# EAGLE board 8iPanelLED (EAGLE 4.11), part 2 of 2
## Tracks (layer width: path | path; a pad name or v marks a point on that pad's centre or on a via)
+15V
  Top 0.762: R75.1 375.29,80.01 375.29,90.17 R74.1 375.29,90.81 375.29,101.6 R73.1 | R81.1 326.39,46.35 326.39,56.52 R80.1 326.39,57.78 326.39,67.94 R79.1 326.39,68.58 326.39,78.74 R78.1 326.39,80.01 326.39,90.17 R77.1 326.39,90.81 326.39,100.97 R76.1 | 232.41,12.7 232.41,13.97 R64.1 | 232.41,12.7 232.41,12.06 220.34,12.06 218.44,13.97 R63.1 217.81,13.97 209.55,13.97 209.55,13.34 208.91,12.7 203.84,12.7 203.84,13.97 R62.1 203.84,14.61 203.84,34.29 R50.1 203.84,35.56 203.84,43.18 | 254,12.06 260.99,12.06 260.99,13.97 R66.1 | 254,12.06 248.92,12.06 247.01,13.97 R65.1 246.38,13.97 246.38,12.7 232.41,12.7 | 254,27.94 247.01,34.92 R53.1 | 254,12.06 254,27.94 | 254,27.94 254,28.57 260.35,34.92 R54.1 | R30.1 261.62,79.38 279.4,79.38 +V2.1 285.75,76.2 297.81,76.2 | R18.1 260.99,100.97 260.99,80.01 R30.1 | R88.1 297.81,34.29 297.81,24.13 R89.1 297.81,23.5 297.81,22.23 285.75,22.23 +V1.1 | 297.81,76.2 297.81,68.58 R85.1 297.81,67.31 297.81,57.78 R86.1 297.81,56.52 297.81,46.35 R87.1 | 297.81,76.2 297.81,78.74 R84.1 297.81,80.01 297.81,90.17 R83.1 297.81,90.81 297.81,100.97 R82.1 | R42.1 260.99,57.78 260.99,78.74 R30.1 | 30.48,12.7 30.48,13.97 R68.1 | 30.48,12.7 30.48,11.43 19.05,11.43 16.51,13.97 R67.1 | 30.48,12.7 36.2,12.7 36.83,13.34 36.83,13.97 45.09,13.97 R69.1 45.09,14.61 47.62,14.61 47.62,15.24 48.26,15.88 59.05,15.88 59.05,14.61 R70.1 59.69,13.97 61.59,12.06 73.66,12.06 73.66,13.97 R71.1 73.66,14.61 73.66,18.41 80.01,24.77 | 80.01,24.77 89.53,34.29 R72.1 | R5.1 75.56,101.6 77.47,101.6 79.38,99.69 88.9,99.69 88.9,101.6 R6.1 | R4.1 60.33,101.6 60.33,99.69 50.8,99.69 48.9,101.6 46.99,101.6 R3.1 46.35,101.6 46.35,99.69 34.92,99.69 33.02,101.6 R2.1
  Top 0.762: R7.1 103.5,101.6 103.5,79.38 R19.1 | R43.1 103.5,34.92 103.5,14.61 R55.1 | 118.11,43.18 118.11,35.56 R44.1 | 118.11,43.18 118.11,56.52 R32.1 118.11,57.78 118.11,78.74 R20.1 118.11,80.01 118.11,100.97 R8.1 | 118.11,43.18 104.14,57.15 R31.1 | 80.01,24.77 92.08,12.7 103.5,12.7 103.5,13.97 R55.1 | R21.1 132.08,79.38 132.08,101.6 R9.1 | 132.08,49.53 132.08,57.15 R33.1 | 132.08,49.53 132.08,34.92 R45.1 | 146.69,49.53 146.69,56.52 R34.1 146.69,57.78 146.69,78.74 R22.1 146.69,80.01 146.69,100.97 R10.1 | 146.69,49.53 146.69,35.56 R46.1 147.32,34.92 149.22,33.02 160.66,33.02 | 146.69,49.53 132.08,49.53 | R23.1 160.66,79.38 160.66,101.6 R11.1 | 160.66,33.02 160.66,14.61 R59.1 | 160.66,33.02 160.66,34.92 R47.1 | 189.23,29.21 189.23,34.92 R49.1 | 189.23,29.21 189.23,14.61 R61.1 | 175.26,29.21 175.26,34.29 R48.1 175.26,35.56 175.26,56.52 R36.1 175.26,57.78 175.26,78.74 R24.1 175.26,80.01 175.26,100.97 R12.1 | 175.26,29.21 175.26,14.61 R60.1 175.26,13.97 175.26,12.06 163.19,12.06 161.29,13.97 R59.1 | 175.26,29.21 189.23,29.21 | 246.38,79.38 246.38,57.15 R41.1 | 246.38,79.38 R29.1 246.38,79.38 | 246.38,79.38 246.38,101.6 R17.1 | R52.1 232.41,35.56 232.41,56.52 R40.1 232.41,57.78 232.41,78.74 R28.1 | 217.81,57.15 217.81,35.56 R51.1 | 217.81,57.15 R39.1 217.81,57.15 | 217.81,79.38 217.81,101.6 R15.1 | 217.81,79.38 R27.1 217.81,79.38 | 217.81,57.15 217.81,79.38 | 189.23,79.38 189.23,57.15 R37.1 189.87,57.15 203.84,43.18 | 189.23,79.38 R25.1 189.23,79.38 | 189.23,79.38 189.23,101.6 R13.1 | 203.84,43.18 203.84,56.52 R38.1 203.84,57.78 203.84,78.74 R26.1 | 146.37,12.7 146.37,12.38 134.94,12.38 133.03,14.29 R57.1
  Top 0.762: 146.37,12.7 146.37,14.29 R58.1 | 146.37,12.7 146.69,12.7 160.66,12.7 160.66,13.97 R59.1 | R55.1 104.14,13.97 106.05,12.06 118.11,12.06 118.11,13.97 R56.1
  Bottom 0.762: 326.39,88.9 326.39,90.17 R77.1 | 326.39,88.9 326.39,87.63 366.39,87.63 374.65,79.38 R75.1 | R42.1 260.99,56.52 260.99,35.56 R54.1 | R87.1 297.81,45.72 297.81,35.56 R88.1 | 326.39,88.9 297.81,88.9 297.81,90.17 R83.1 | R5.1 74.93,101.6 66.67,101.6 66.67,100.33 66.04,99.69 60.96,99.69 60.96,100.97 R4.1 | 103.5,66.67 103.5,79.38 R19.1 | 103.5,66.67 103.5,57.15 R31.1 | 103.5,66.67 91.44,66.67 89.53,68.58 89.53,100.97 R6.1 | R21.1 132.08,79.38 132.08,57.15 R33.1 | 160.66,57.15 160.66,35.56 R47.1 | 160.66,57.15 R35.1 160.66,57.15 | 160.66,57.15 160.66,79.38 R23.1 | R16.1 232.41,100.97 232.41,80.01 R28.1 233.04,79.38 234.31,78.11 234.31,77.47 237.49,77.47 238.12,78.11 238.12,79.38 246.38,79.38 R29.1 | R14.1 203.84,100.97 203.84,80.01 R26.1 | R50.1 203.84,34.29 203.84,33.66 208.91,33.66 209.55,34.29 209.55,34.92 217.81,34.92 R51.1 218.44,34.92 218.44,33.02 222.25,33.02 224.16,34.92 231.78,34.92 R52.1 | R24.1 175.9,79.38 177.8,77.47 189.23,77.47 189.23,79.38 R25.1 | R1.1 18.41,101.6 20.32,101.6 22.23,99.69 31.75,99.69 31.75,101.6 R2.1 | 118.11,22.86 118.11,34.29 R44.1 | 118.11,22.86 118.11,14.61 R56.1 | 118.11,22.86 137.16,22.86 139.7,25.4 139.7,27.3 146.69,34.29 R46.1
AC0
  Bottom 0.381: T43.2 93.34,48.26 88.27,53.34 88.27,113.03 109.22,133.99 118.75,133.99 118.75,131.44 D40TOP.4 118.75,128.91 118.75,127.64 114.94,123.83 E40.7
AC1
  Top 0.381: D40BOT.2 115.57,128.91 115.57,128.27 113.67,126.36 110.49,126.36 110.49,121.92 109.86,121.28 E40.4
  Bottom 0.381: T44.2 107.95,48.26 112.39,52.7 112.39,118.11 109.86,120.65 E40.4
AC2
  Top 0.381: T45.2 122.56,48.26 130.81,56.52 130.81,57.78 131.44,58.42 135.25,58.42 135.25,56.52 135.89,55.88 139.7,55.88 139.7,96.52 135.25,100.97 135.25,103.5 130.81,107.95 130.81,122.56 131.44,123.19 E40.21
  Bottom 0.381: D40TOP.12 131.44,128.91 131.44,123.83 E40.21
AC3
  Top 0.381: D40BOT.9 127,128.91 126.36,128.27 126.36,127.64 123.19,124.46 123.19,121.92 122.56,121.28 E40.14
  Bottom 0.381: T46.2 136.53,48.26 127.64,57.15 127.64,71.75 119.38,80.01 119.38,118.75 121.28,120.65 E40.14
AC4
  Bottom 0.381: T47.2 151.13,48.26 154.94,52.07 154.94,106.05 149.86,111.12 148.59,111.12 146.05,113.67 146.05,122.56 145.41,123.19 E40.31 144.15,123.83 140.34,127.64 140.34,128.27 139.7,128.91 D40TOP.17
AC5
  Top 0.381: 161.93,51.44 153.67,59.69 153.67,114.3 151.76,116.2 140.34,116.2 140.34,120.65 E40.28 | 161.93,51.44 165.1,48.26 T48.2 | 161.93,51.44 167.64,57.15 167.64,116.2 158.12,116.2 152.4,121.92 152.4,132.72 139.06,132.72 138.43,132.08 138.43,131.44 D40BOT.16
AC6
  Bottom 0.381: 204.47,124.46 204.47,128.91 E40TOP.4 | 204.47,124.46 203.84,123.83 F40.7 | 204.47,124.46 204.47,120.02 202.56,118.11 202.56,100.33 200.03,97.79 200.03,65.41 193.68,65.41 187.96,59.69 187.96,56.52 179.71,48.26 T49.2
AC7
  Top 0.381: 196.85,119.38 197.49,119.38 197.49,120.65 F40.4 | 196.85,119.38 194.94,119.38 187.96,112.39 187.96,53.98 193.68,48.26 T50.2 | 196.85,119.38 196.85,125.09 198.12,125.09 201.29,128.27 201.29,128.91 E40BOT.2
AC8
  Bottom 0.381: 217.17,127 217.17,128.91 E40TOP.12 | 217.17,127 217.17,120.02 216.53,119.38 216.53,56.52 208.28,48.26 T51.2 | 217.17,127 220.34,123.83 F40.21
AC9
  Top 0.381: E40BOT.9 212.72,128.91 212.09,128.27 212.09,121.92 211.46,121.28 F40.14
  Bottom 0.381: T52.2 222.25,47.62 233.68,47.62 233.68,33.66 224.16,24.13 201.29,24.13 201.29,73.66 205.1,77.47 205.1,115.57 210.19,120.65 F40.14
AC10
  Top 0.381: T53.2 236.85,48.26 239.4,50.8 239.4,115.57 234.95,120.02 234.95,122.56 234.31,123.19 F40.31
  Bottom 0.381: E40TOP.17 225.43,128.91 226.06,128.27 226.06,127.64 227.33,126.36 233.04,126.36 233.04,123.83 F40.31
AC11
  Top 0.381: E40BOT.16 224.16,131.44 224.16,132.08 224.79,132.72 253.37,132.72 253.37,52.07 249.56,48.26 T54.2
  Bottom 0.381: T54.2 248.92,48.26 239.4,57.78 239.4,70.48 228.6,81.28 228.6,120.65 F40.28
AND
  Top 0.381: T82.2 317.5,106.68 317.5,113.67 310.51,120.65 D40.2 309.25,121.28 308.61,121.92 308.61,128.91 314.32,128.91 F40BOT.1
BREAK
  Top 0.381: T81.2 346.07,50.8 346.07,48.9 341.63,44.45 331.47,44.45 331.47,128.91 F40BOT.12
  Bottom 0.381: D40.22 334.64,121.28 334.01,121.92 334.01,124.46 333.38,125.09 316.23,125.09 316.23,116.2 309.88,109.86 309.88,101.6 300.36,92.08 296.55,92.08 296.55,87 304.8,78.74 304.8,69.22 309.25,64.77 334.64,64.77 334.64,57.15 338.45,53.34 346.07,53.34 346.07,50.8 T81.2
CA
  Top 0.381: T80.2 346.71,62.23 349.25,64.77 349.25,120.02 348.62,120.65 D40.32 347.35,121.28 346.71,121.92 346.71,125.09 344.81,125.09 341.63,128.27 341.63,128.91 F40BOT.18
DCA
  Top 0.381: F40BOT.4 318.77,128.91 318.77,127 316.23,124.46 316.23,121.92 316.87,121.28 D40.8
  Bottom 0.381: T85.2 318.13,73.03 334.64,73.03 334.64,74.93 337.82,78.11 376.56,78.11 376.56,80.01 367.67,88.9 327.66,88.9 327.66,91.44 315.6,103.5 314.32,103.5 314.32,113.03 317.5,116.2 317.5,120.65 D40.8
DEFER
  Top 0.381: T78.2 346.71,84.45 347.98,85.72 347.98,113.67 341,120.65 D40.26 339.73,121.28 339.09,121.92 339.09,124.46 337.19,126.36 337.19,128.27 336.55,128.91 F40BOT.15
DF0
  Top 0.381: T1.2 8.26,114.94 20.95,114.94 20.95,120.65 23.5,123.19 C40.1
  Bottom 0.381: C40TOP.1 28.57,128.91 24.77,125.09 24.77,123.83 C40.1
DF1
  Top 0.381: 33.02,114.94 33.66,114.94 33.66,120.65 C40.10 | 33.02,114.94 22.23,114.94 T2.2 | 33.02,114.94 33.02,124.46 34.29,125.73 34.29,128.27 34.92,128.91 C40BOT.5
DF2
  Top 0.381: T3.2 36.2,114.94 35.56,115.57 35.56,122.56 36.2,123.19 C40.11
  Bottom 0.381: C40TOP.6 36.2,128.91 36.2,123.83 C40.11
EXECUTE
  Top 0.381: F40BOT.16 338.45,128.91 338.45,127.64 341.63,124.46 341.63,121.92 342.26,121.28 D40.28
  Bottom 0.381: T77.2 346.71,95.25 347.98,96.52 347.98,114.94 342.9,120.02 342.9,120.65 D40.28
FETCH
  Top 0.381: T76.2 346.07,106.68 346.07,113.03 338.45,120.65 D40.24 337.19,121.28 336.55,121.92 336.55,124.46 335.28,125.73 335.28,128.91 F40BOT.14
GND
  Top 0.762: 358.77,95.25 358.77,87 357.5,85.72 T75.1 | 358.77,95.25 357.5,96.52 T74.1 | 358.77,95.25 358.77,106.05 357.5,107.31 T73.1 | F40BOT.13 333.38,128.91 333.38,123.83 D40.19 | 342.9,59.05 342.9,50.8 344.17,49.53 T81.1 | 342.9,59.05 344.17,60.33 T80.1 | 342.9,70.48 344.17,71.75 T79.1 | 342.9,70.48 342.9,59.05 | 342.9,81.28 344.17,82.55 T78.1 | 342.9,81.28 342.9,70.48 | 342.9,92.71 344.17,93.98 T77.1 | 342.9,92.71 342.9,81.28 | 342.9,92.71 342.9,103.5 344.17,104.78 T76.1 344.17,105.41 333.38,116.2 333.38,120.65 D40.20 | 314.32,36.83 314.32,28.57 315.6,27.3 T89.1 | 314.32,36.83 315.6,38.1 T88.1 | 314.32,48.26 315.6,49.53 T87.1 | 314.32,42.55 314.32,36.83 | 314.32,42.55 314.32,48.26 | 314.32,59.05 315.6,60.33 T86.1 | 314.32,48.26 314.32,59.05 | 314.32,70.48 315.6,71.75 T85.1 | 314.32,59.05 314.32,70.48 | 314.32,81.28 315.6,82.55 T84.1 | 314.32,70.48 314.32,81.28 | 314.32,92.71 315.6,93.98 T83.1 | 314.32,81.28 314.32,92.71 | 314.32,92.71 314.32,93.34 | 314.32,93.34 314.32,103.5 315.6,104.78 T82.1 | 314.32,93.34 306.07,101.6 306.07,103.5 285.75,103.5 GND2.1 | 73.66,112.39 78.11,112.39 T6.1 | 73.66,112.39 66.67,112.39 T5.1 66.04,112.39 64.77,111.12 52.07,111.12 52.07,112.39 T4.1 | 23.5,111.12 19.68,111.12 19.05,111.76 19.05,112.39 9.53,112.39 T1.1 | 23.5,111.12 23.5,112.39 T2.1 | C40BOT.13 47.62,128.91 47.62,123.83 C40.19 46.35,123.19 45.09,123.19 C40.17 43.81,123.19 43.81,121.28 C40.18 45.09,120.65 46.35,120.65 C40.20 | 23.5,111.12 37.47,111.12 37.47,112.39 T3.1 | T68.1 22.23,25.4 22.23,23.5 33.66,23.5 35.56,25.4 T69.1 36.83,25.4 46.35,25.4 46.35,24.13 46.99,23.5 50.16,23.5 50.16,25.4 T70.1 50.8,25.4 60.33,25.4 62.23,23.5 64.14,23.5 64.14,25.4 T71.1 65.41,25.4 65.41,30.48 73.66,38.73
  Top 0.762: 73.66,38.73 80.64,45.72 T72.1 80.64,46.35 90.81,46.35 90.81,47.62 95.25,52.07 | 73.66,38.73 73.66,112.39 | T41.1 238.12,68.58 238.12,90.17 T29.1 238.12,90.81 238.12,93.98 | 238.12,93.98 238.12,112.39 T17.1 | 238.12,33.66 238.12,45.72 T53.1 | 238.12,29.21 238.12,33.66 | 238.12,29.21 238.12,25.4 T65.1 | 238.12,33.66 250.19,45.72 T54.1 250.82,45.72 252.73,43.81 252.73,38.73 278.76,38.73 GND1.1 283.85,40.64 283.85,42.55 314.32,42.55 | 238.12,29.21 250.82,29.21 252.73,27.3 252.73,26.67 252.09,26.04 T66.1 | F40.19 217.81,123.19 216.53,123.19 F40.17 215.9,123.19 215.9,121.28 F40.18 216.53,120.65 217.81,120.65 F40.20 | 224.16,29.21 224.16,45.09 | 224.16,29.21 224.16,26.67 223.52,26.04 T64.1 | 224.16,45.09 223.52,45.72 T52.1 | 224.16,67.31 223.52,67.94 T40.1 | 224.16,45.09 224.16,67.31 | 224.16,89.53 223.52,90.17 T28.1 | 224.16,67.31 224.16,89.53 | 224.16,89.53 224.16,93.98 | 224.16,93.98 224.16,111.76 223.52,112.39 T16.1 | 224.16,29.21 238.12,29.21 | 224.16,93.98 238.12,93.98 | T55.1 95.25,25.4 95.25,45.72 T43.1 95.25,46.35 95.25,49.53 | 95.25,49.53 95.25,52.07 | 95.25,52.07 95.25,67.94 T31.1 | T7.1 95.25,112.39 95.25,90.81 T19.1 | 138.43,29.21 138.43,45.09 137.79,45.72 T46.1 | 138.43,29.21 138.43,26.67 137.79,26.04 T58.1 | 109.86,29.21 109.86,45.09 | 109.86,29.21 109.86,26.67 109.22,26.04 T56.1 | 109.86,45.09 109.22,45.72 T44.1 | 123.83,29.21 123.83,45.72 T45.1 | 123.83,29.21 123.83,25.4 T57.1 | T33.1 123.83,68.58 123.83,90.17 T21.1 123.83,90.81 123.83,112.39 T9.1 | 123.83,29.21 109.86,29.21 | 138.43,29.21 123.83,29.21 | 95.25,49.53 109.86,49.53 109.86,45.09 | D40BOT.13 133.35,128.91 133.35,127.64 130.18,124.46 130.18,123.83 E40.19
  Top 0.762: E40.18 127,121.28 127,123.19 E40.17 | T34.1 137.79,68.58 138.43,69.22 138.43,89.53 137.79,90.17 T22.1 | 152.4,97.16 152.4,90.81 T23.1 152.4,90.17 152.4,68.58 T35.1 152.4,67.94 152.4,46.35 T47.1 152.4,45.72 161.93,45.72 161.93,45.09 162.56,44.45 166.37,44.45 166.37,45.72 T48.1 | 152.4,97.16 152.4,112.39 T11.1 | 152.4,97.16 149.22,100.33 149.22,100.97 137.79,112.39 T10.1 | T63.1 209.55,25.4 209.55,45.72 T51.1 209.55,46.35 209.55,67.94 T39.1 209.55,68.58 209.55,90.17 T27.1 209.55,90.81 209.55,93.98 | 209.55,93.98 209.55,112.39 T15.1 | T50.1 194.94,45.72 195.58,45.09 195.58,25.4 T62.1 | T37.1 180.97,68.58 180.97,90.17 T25.1 180.97,90.81 180.97,112.39 T13.1 180.97,113.03 180.97,132.72 218.44,132.72 219.07,132.08 219.07,131.44 E40BOT.13 | 195.58,89.53 194.94,90.17 T26.1 | 195.58,89.53 195.58,69.22 194.94,68.58 T38.1 | 195.58,93.98 195.58,89.53 | 195.58,93.98 195.58,111.76 194.94,112.39 T14.1 | 209.55,93.98 195.58,93.98 | 138.43,29.21 152.4,29.21 152.4,25.4 T59.1
  Bottom 0.762: D40.18 330.83,120.65 332.11,120.65 D40.20 | D40.19 332.11,123.19 330.83,123.19 D40.17 329.56,123.19 329.56,121.28 D40.18 | T75.1 356.87,85.72 347.98,85.72 347.98,83.19 347.35,82.55 344.81,82.55 T78.1 | D40.18 329.56,120.65 329.56,115.57 318.77,104.78 316.23,104.78 T82.1 | T4.1 52.07,112.39 50.8,111.12 47.62,111.12 47.62,120.65 C40.20 | T3.1 38.1,113.03 43.81,118.75 43.81,120.65 C40.18 | T67.1 8.26,25.4 17.78,25.4 17.78,24.13 18.41,23.5 21.59,23.5 21.59,25.4 T68.1 | 252.73,88.27 252.73,89.53 | 252.73,88.27 252.73,69.22 252.09,68.58 T42.1 | 252.73,89.53 252.09,90.17 T30.1 | 252.73,89.53 252.73,111.76 252.09,112.39 T18.1 | T16.1 223.52,112.39 222.25,111.12 219.07,111.12 219.07,120.65 F40.20 | 252.73,88.27 238.12,88.27 238.12,90.17 T29.1 | 109.86,87 109.86,89.53 | 109.86,87 109.86,69.22 109.22,68.58 T32.1 | 109.86,89.53 109.22,90.17 T20.1 | 109.86,89.53 109.86,111.76 109.22,112.39 T8.1 | 95.25,87 95.25,68.58 T31.1 | 95.25,87 95.25,90.17 T19.1 | 95.25,87 109.86,87 | T33.1 123.83,67.94 123.83,46.35 T45.1 | E40.18 127.64,120.65 128.91,120.65 E40.20 130.18,120.65 130.18,92.71 133.99,88.9 137.79,88.9 137.79,90.17 T22.1 137.79,90.81 138.43,91.44 138.43,111.76 137.79,112.39 T10.1 | E40.17 127.64,123.19 128.91,123.19 E40.19 | T12.1 166.37,112.39 165.1,111.12 152.4,111.12 152.4,112.39 T11.1 | 165.74,23.5 163.83,23.5 161.93,25.4 152.4,25.4 T59.1 | 165.74,23.5 165.74,25.4 T60.1 167,25.4 167,32.38 | 167,45.09 166.37,45.72 T48.1 | 167,45.09 167,32.38 | 167,67.31 166.37,67.94 T36.1 | 167,54.61 167,45.09 | 167,54.61 167,67.31 | 179.07,23.5 179.71,24.13 179.71,24.77 180.34,25.4 T61.1 | 165.74,23.5 179.07,23.5
  Bottom 0.762: 167,32.38 180.34,45.72 T49.1 | 167,54.61 180.34,67.94 T37.1 180.97,67.94 180.97,66.67 193.68,66.67 194.94,67.94 T38.1 | 179.07,23.5 192.41,23.5 194.31,25.4 T62.1 | 167,67.31 167,89.53 166.37,90.17 T24.1 | T64.1 223.52,26.04 224.16,26.67 224.16,27.3 222.25,29.21 209.55,29.21 209.55,25.4 T63.1
IF0
  Top 0.381: 50.8,114.94 51.44,115.57 51.44,120.65 C40.24 | 50.8,114.94 T4.2 50.8,114.94 | 50.8,114.94 50.8,124.46 49.53,125.73 49.53,128.91 C40BOT.14
IF1
  Top 0.381: T5.2 64.77,114.94 55.88,114.94 55.88,122.56 55.24,123.19 C40.25
  Bottom 0.381: C40TOP.14 49.53,128.91 49.53,128.27 53.98,123.83 C40.25
IF2
  Top 0.381: C40BOT.19 57.15,128.91 63.5,128.91 63.5,121.92 64.14,121.28 C40.34
  Bottom 0.381: T6.2 79.38,111.12 67.94,111.12 67.94,118.11 65.41,120.65 C40.34
ION
  Top 0.381: F40BOT.19 342.9,128.91 349.25,128.91 349.25,121.92 349.88,121.28 D40.34
  Bottom 0.381: T73.2 354.96,106.68 351.15,110.49 351.15,120.65 D40.34
IOT
  Bottom 0.381: 333.38,127.64 316.87,127.64 313.69,124.46 313.69,120.02 294,100.33 294,87 300.36,80.64 300.36,47.62 311.79,47.62 317.5,41.91 317.5,40.01 T88.2 | 333.38,127.64 333.38,128.91 F40TOP.13 | 333.38,127.64 337.19,123.83 D40.23
ISZ
  Top 0.381: F40BOT.3 317.5,128.91 316.87,128.27 316.87,127.64 313.69,124.46 313.69,121.92 314.32,121.28 D40.6
  Bottom 0.381: T84.2 317.5,83.82 317.5,81.92 311.15,75.56 306.07,75.56 306.07,70.48 306.7,69.85 347.98,69.85 347.98,50.16 345.44,47.62 319.4,47.62 319.4,51.44 312.42,58.42 301.62,58.42 301.62,80.64 295.27,87 295.27,97.16 314.96,116.84 314.96,120.65 D40.6
JMP
  Top 0.381: T87.2 318.13,50.8 321.94,54.61 321.94,120.65 D40.12 321.94,121.28 321.31,121.92 321.31,124.46 321.94,125.09 321.94,128.91 F40BOT.6
JMS
  Top 0.381: T86.2 318.13,62.23 320.68,64.77 320.68,120.65 D40.10 319.4,121.28 318.77,121.92 318.77,124.46 320.04,125.73 320.04,128.27 320.68,128.91 F40BOT.5
LINK
  Top 0.381: C40BOT.16 52.7,128.91 52.7,128.27 55.88,125.09 58.42,125.09 58.42,121.92 57.78,121.28 C40.28
  Bottom 0.381: T72.2 79.38,48.26 57.78,69.85 57.78,120.65 C40.28
MA0
  Bottom 0.381: 108.58,125.09 106.05,125.09 105.41,124.46 105.41,92.71 93.98,92.71 T19.2 | 108.58,125.09 108.58,123.83 E40.3 | 108.58,125.09 112.39,125.09 115.57,128.27 115.57,128.91 D40TOP.2
MA1
  Top 0.381: E40.8 113.67,120.65 113.67,118.11 109.22,118.11 105.41,114.3 105.41,95.25 107.95,92.71 T20.2 107.95,92.08 107.95,89.53 110.49,87 110.49,55.88 107.31,55.88 106.05,57.15 106.05,60.33 90.81,75.56 90.81,132.72 118.11,132.72 118.75,132.08 118.75,131.44 D40BOT.4
MA2
  Bottom 0.381: 123.19,122.56 123.19,120.02 125.09,118.11 125.09,95.25 122.56,92.71 T21.2 | 123.19,122.56 122.56,123.19 E40.13 | 123.19,122.56 123.19,128.27 123.83,128.91 D40TOP.7
MA3
  Top 0.381: D40BOT.12 131.44,128.91 131.44,127.64 128.27,124.46 128.27,107.95 133.99,102.23 133.99,95.25 136.53,92.71 T22.2
  Bottom 0.381: T22.2 136.53,92.71 133.99,95.25 133.99,119.38 132.72,120.65 E40.22
MA4
  Bottom 0.381: T23.2 150.5,92.71 141.6,101.6 141.6,119.38 140.97,120.02 140.97,122.56 140.34,123.19 E40.27 139.06,123.83 137.16,125.73 137.16,128.27 136.53,128.91 D40TOP.15
MA5
  Top 0.381: T24.2 165.1,92.71 162.56,95.25 162.56,107.95 151.13,119.38 145.41,119.38 145.41,120.65 E40.32 144.15,121.28 143.51,121.92 143.51,124.46 141.6,126.36 141.6,128.91 D40BOT.18
MA6
  Bottom 0.381: T25.2 179.71,92.71 181.61,94.61 181.61,111.12 193.68,123.19 193.68,123.83 194.94,125.09 197.49,125.09 197.49,123.83 F40.3 198.75,123.83 201.29,126.36 201.29,128.91 E40TOP.2
MA7
  Top 0.381: F40.8 202.56,121.28 201.93,121.92 201.93,125.73 204.47,128.27 204.47,128.91 E40BOT.4
  Bottom 0.381: T26.2 193.68,92.71 201.29,100.33 201.29,119.38 202.56,120.65 F40.8
MA8
  Bottom 0.381: T27.2 208.28,92.71 212.09,96.52 212.09,122.56 211.46,123.19 F40.13 210.19,123.83 210.19,128.27 209.55,128.91 E40TOP.7
MA9
  Top 0.381: 219.71,120.02 219.71,95.25 222.25,92.71 T28.2 | 219.71,120.02 220.34,120.65 F40.22 | 219.71,120.02 219.71,124.46 217.81,126.36 217.81,128.91 E40BOT.12
MA10
  Bottom 0.381: 233.68,95.25 236.22,92.71 T29.2 | 233.68,95.25 233.68,116.2 229.87,120.02 229.87,122.56 229.24,123.19 F40.27 | 233.68,95.25 233.68,87 241.3,87 248.28,80.01 248.28,57.78 253.37,52.7 253.37,24.13 248.92,24.13 248.28,24.77 248.28,28.57 235.59,28.57 233.68,26.67 233.68,21.59 255.91,21.59 257.18,22.86 257.18,132.72 222.88,132.72 222.88,132.08 222.25,131.44 E40TOP.15
MA11
  Top 0.381: E40BOT.18 227.33,128.91 227.33,128.27 229.24,126.36 248.28,126.36 248.28,95.25 250.82,92.71 T30.2
  Bottom 0.381: T30.2 250.82,92.71 239.4,104.14 239.4,115.57 234.31,120.65 F40.32
MB0
  Bottom 0.381: T31.2 93.34,70.48 90.81,73.03 90.81,114.3 109.22,132.72 117.47,132.72 117.47,131.44 D40TOP.3 117.47,128.91 117.47,127.64 116.2,127.64 112.39,123.83 E40.5
MB1
  Top 0.381: T32.2 107.95,70.48 102.23,76.2 102.23,112.39 109.22,119.38 111.12,119.38 111.12,120.65 E40.6 112.39,121.28 113.03,121.92 113.03,125.09 114.3,125.09 116.84,127.64 116.84,128.27 117.47,128.91 D40BOT.3
MB2
  Bottom 0.381: 125.73,123.19 125.73,128.91 D40TOP.8 | 125.73,123.19 125.73,120.02 126.36,119.38 126.36,87.63 139.06,74.93 139.06,44.45 134.62,44.45 126.36,52.7 126.36,69.85 122.56,69.85 T33.2 | 125.73,123.19 125.09,123.19 E40.15
MB3
  Top 0.381: T34.2 136.53,70.48 125.09,81.92 125.09,120.65 E40.16 125.09,121.28 125.73,121.92 125.73,125.09 127,125.09 129.54,127.64 129.54,128.27 130.18,128.91 D40BOT.11
MB4
  Bottom 0.381: T35.2 151.13,70.48 153.67,73.03 153.67,96.52 149.22,100.97 149.22,109.22 143.51,114.94 143.51,122.56 142.88,123.19 E40.29 141.6,123.83 138.43,127 138.43,128.91 D40TOP.16
MB5
  Top 0.381: T36.2 165.1,70.48 154.94,80.64 154.94,114.3 151.13,118.11 142.88,118.11 142.88,120.65 E40.30 141.6,121.28 140.97,121.92 140.97,124.46 140.34,125.09 140.34,128.27 139.7,128.91 D40BOT.17
MB6
  Bottom 0.381: T37.2 179.71,70.48 191.13,70.48 191.13,97.16 199.39,105.41 199.39,122.56 200.03,123.19 F40.5 201.29,123.83 202.56,125.09 202.56,128.27 203.2,128.91 E40TOP.3
MB7
  Top 0.381: 199.39,118.11 200.03,118.11 200.03,120.65 F40.6 | 199.39,118.11 194.94,118.11 191.13,114.3 191.13,73.03 193.68,70.48 T38.2 | 199.39,118.11 199.39,124.46 202.56,127.64 202.56,128.27 203.2,128.91 E40BOT.3
MB8
  Bottom 0.381: T39.2 208.28,70.48 214.63,76.83 214.63,122.56 214,123.19 F40.15 212.72,123.83 211.46,125.09 211.46,128.91 E40TOP.8
MB9
  Top 0.381: T40.2 222.25,69.85 219.71,69.85 219.71,34.29 219.07,33.66 214,33.66 214,120.65 F40.16 214,121.28 214.63,121.92 214.63,124.46 215.26,125.09 215.26,128.27 215.9,128.91 E40BOT.11
MB10
  Bottom 0.381: 227.33,125.09 227.33,79.38 236.22,70.48 T41.2 | 227.33,125.09 224.16,128.27 224.16,128.91 E40TOP.16 | 227.33,125.09 229.24,125.09 230.5,123.83 F40.29
MB11
  Top 0.381: 229.87,125.09 225.43,125.09 225.43,128.91 E40BOT.17 | 229.87,125.09 236.85,125.09 240.66,121.28 240.66,55.88 247.65,55.88 248.28,56.52 248.28,69.85 250.82,69.85 T42.2 | 229.87,125.09 229.87,121.92 230.5,121.28 F40.30
MQ0
  Bottom 0.381: T55.2 93.98,27.3 95.89,27.3 102.23,33.66 115.57,33.66 115.57,122.56 116.2,123.19 E40.9 117.47,123.83 120.02,126.36 120.02,128.27 120.65,128.91 D40TOP.5
MQ1
  Top 0.381: D40BOT.1 114.3,128.91 107.95,128.91 107.95,121.92 107.31,121.28 E40.2
  Bottom 0.381: T56.2 107.31,27.3 97.16,27.3 97.16,25.4 95.89,24.13 88.27,24.13 88.27,38.1 93.34,43.18 105.41,43.18 105.41,52.7 111.12,58.42 111.12,116.84 107.31,120.65 E40.2
MQ2
  Bottom 0.381: T57.2 122.56,27.3 131.44,36.2 140.34,36.2 140.34,115.57 135.89,120.02 135.89,122.56 135.25,123.19 E40.23 133.99,123.83 133.99,128.27 133.35,128.91 D40TOP.13
MQ3
  Top 0.381: D40BOT.6 121.92,128.91 121.92,128.27 118.11,124.46 118.11,121.92 118.75,121.28 E40.12
  Bottom 0.381: T58.2 135.89,27.3 125.09,27.3 125.09,24.77 124.46,24.13 119.38,24.13 119.38,76.2 116.84,78.74 116.84,118.75 118.75,120.65 E40.12
MQ4
  Bottom 0.381: T59.2 151.13,27.3 159.38,35.56 159.38,104.14 165.1,109.86 167.64,109.86 167.64,114.3 163.19,118.75 151.13,118.75 151.13,120.02 147.96,123.19 E40.33 146.69,123.83 146.69,125.09 144.78,125.09 141.6,128.27 141.6,128.91 D40TOP.18
MQ5
  Top 0.381: T60.2 165.1,27.94 168.91,31.75 168.91,118.75 153.67,133.99 136.53,133.99 136.53,131.44 D40BOT.15 136.53,128.91 135.89,128.27 135.89,121.92 136.53,121.28 E40.26
MQ6
  Bottom 0.381: F40.9 206.38,123.83 206.38,128.91 E40TOP.5 206.38,131.44 206.38,133.99 257.18,133.99 258.44,132.72 258.44,15.88 206.38,15.88 200.03,22.23 200.03,28.57 193.04,28.57 192.41,27.94 192.41,27.3 179.71,27.3 T61.2
MQ7
  Top 0.381: 194.31,120.02 194.94,120.65 F40.2 | 194.31,120.02 186.69,112.39 186.69,53.98 191.13,49.53 191.13,30.48 193.68,27.94 T62.2 | 194.31,120.02 194.31,128.91 200.03,128.91 E40BOT.1
MQ8
  Bottom 0.381: T63.2 207.65,27.3 202.56,32.38 202.56,38.1 208.91,44.45 219.71,44.45 219.71,97.16 224.79,102.23 224.79,122.56 224.16,123.19 F40.23 222.88,123.83 219.71,127 219.71,128.27 219.07,128.91 E40TOP.13
MQ9
  Top 0.381: 209.55,120.02 208.91,120.65 F40.12 | 209.55,120.02 210.82,118.75 210.82,27.3 221.62,27.3 T64.2 | 209.55,120.02 209.55,124.46 208.28,125.73 208.28,128.91 E40BOT.6
MQ10
  Bottom 0.381: T65.2 236.85,27.3 247.01,27.3 247.01,24.77 248.92,22.86 255.91,22.86 255.91,111.76 244.47,123.19 236.85,123.19 F40.33 235.59,123.83 235.59,127.64 227.97,127.64 227.33,128.27 227.33,128.91 E40TOP.18
MQ11
  Top 0.381: E40BOT.15 222.25,128.91 222.88,128.27 222.88,126.36 224.79,124.46 224.79,121.92 225.43,121.28 F40.26
  Bottom 0.381: T66.2 250.82,27.94 239.4,39.37 239.4,52.07 226.06,65.41 226.06,120.65 F40.26
N$1
  Top 0.381: T1.3 6.99,112.39 7.62,111.76 7.62,107.95 DF0.B
N$2
  Bottom 0.381: T2.3 20.95,112.39 21.59,111.76 21.59,107.95 DF1.B
N$3
  Bottom 0.381: T3.3 35.56,112.39 36.2,111.76 36.2,107.95 DF2.B
N$4
  Top 0.381: T4.3 49.53,112.39 50.16,111.76 50.16,107.95 IF0.B
N$5
  Bottom 0.381: T5.3 64.14,112.39 64.77,111.76 64.77,107.95 IF1.B
N$6
  Top 0.381: T6.3 80.64,112.39 80.64,108.58 80.01,107.95 IF2.B
N$7
  Top 0.381: T7.3 92.71,112.39 93.34,111.76 93.34,107.95 PC0.B
N$8
  Top 0.381: T8.3 106.68,112.39 107.31,111.76 107.31,107.95 PC1.B
N$9
  Top 0.381: T9.3 121.28,112.39 121.92,111.76 121.92,107.95 PC2.B
N$10
  Top 0.381: T10.3 135.25,112.39 135.89,111.76 135.89,107.95 PC3.B
N$11
  Top 0.381: T11.3 149.86,112.39 150.5,111.76 150.5,107.95 PC4.B
N$12
  Top 0.381: T12.3 163.83,112.39 164.47,111.76 164.47,107.95 PC5.B
N$13
  Top 0.381: T13.3 178.44,112.39 179.07,111.76 179.07,107.95 PC6.B
N$14
  Top 0.381: T14.3 192.41,112.39 193.04,111.76 193.04,107.95 PC7.B
N$15
  Top 0.381: T15.3 207.01,112.39 207.65,111.76 207.65,107.95 PC8.B
N$16
  Top 0.381: T16.3 220.98,112.39 221.62,111.76 221.62,107.95 PC9.B
N$17
  Top 0.381: T17.3 235.59,112.39 236.22,111.76 236.22,107.95 PC10.B
N$18
  Top 0.381: T18.3 249.56,112.39 250.19,111.76 250.19,107.95 PC11.B
N$19
  Top 0.381: T19.3 92.71,90.17 93.34,89.53 93.34,85.72 MA0.B
N$20
  Top 0.381: T20.3 106.68,90.17 106.68,86.36 107.31,85.72 MA1.B
N$21
  Top 0.381: T21.3 121.28,90.17 121.92,89.53 121.92,85.72 MA2.B
N$22
  Top 0.381: T22.3 135.25,90.17 135.89,89.53 135.89,85.72 MA3.B
N$23
  Top 0.381: T23.3 149.86,90.17 150.5,89.53 150.5,85.72 MA4.B
N$24
  Top 0.381: T24.3 163.83,90.17 164.47,89.53 164.47,85.72 MA5.B
N$25
  Top 0.381: T25.3 178.44,90.17 179.07,89.53 179.07,85.72 MA6.B
N$26
  Top 0.381: T26.3 192.41,90.17 193.04,89.53 193.04,85.72 MA7.B
N$27
  Top 0.381: T27.3 207.01,90.17 207.65,89.53 207.65,85.72 MA8.B
N$28
  Top 0.381: T28.3 220.98,90.17 221.62,89.53 221.62,85.72 MA9.B
N$29
  Top 0.381: T29.3 235.59,90.17 236.22,89.53 236.22,85.72 MA10.B
N$30
  Top 0.381: T30.3 249.56,90.17 250.19,89.53 250.19,85.72 MA11.B
N$31
  Top 0.381: T31.3 92.71,67.94 93.34,67.31 93.34,63.5 MB0.B
N$32
  Top 0.381: T32.3 106.68,67.94 107.31,67.31 107.31,63.5 MB1.B
N$33
  Top 0.381: T33.3 121.28,67.94 121.92,67.31 121.92,63.5 MB2.B
N$34
  Top 0.381: T34.3 135.25,67.94 135.89,67.31 135.89,63.5 MB3.B
N$35
  Top 0.381: T35.3 149.86,67.94 150.5,67.31 150.5,63.5 MB4.B
N$36
  Top 0.381: T36.3 163.83,67.94 164.47,67.31 164.47,63.5 MB5.B
N$37
  Top 0.381: T37.3 178.44,67.94 179.07,67.31 179.07,63.5 MB6.B
N$38
  Top 0.381: T38.3 192.41,67.94 193.04,67.31 193.04,63.5 MB7.B
N$39
  Top 0.381: T39.3 207.01,67.94 207.65,67.31 207.65,63.5 MB8.B
N$40
  Top 0.381: T40.3 220.98,67.94 221.62,67.31 221.62,63.5 MB9.B
N$41
  Top 0.381: T41.3 235.59,67.94 236.22,67.31 236.22,63.5 MB10.B
N$42
  Top 0.381: T42.3 249.56,67.94 250.19,67.31 250.19,63.5 MB11.B
N$43
  Top 0.381: T43.3 92.71,45.72 93.34,45.09 93.34,41.27 AC0.B
N$44
  Top 0.381: T44.3 106.68,45.72 107.31,45.09 107.31,41.27 AC1.B
N$45
  Top 0.381: T45.3 121.28,45.72 121.92,45.09 121.92,41.27 AC2.B
N$46
  Top 0.381: T46.3 135.25,45.72 135.89,45.09 135.89,41.27 AC3.B
N$47
  Top 0.381: T47.3 149.86,45.72 150.5,45.09 150.5,41.27 AC4.B
N$48
  Bottom 0.381: T48.3 163.83,45.72 164.47,45.09 164.47,41.27 AC5.B
N$49
  Top 0.381: T49.3 178.44,45.72 179.07,45.09 179.07,41.27 AC6.B
N$50
  Top 0.381: T50.3 192.41,45.72 193.04,45.09 193.04,41.27 AC7.B
N$51
  Top 0.381: T51.3 207.01,45.72 207.65,45.09 207.65,41.27 AC8.B
N$52
  Top 0.381: T52.3 220.98,45.72 221.62,45.09 221.62,41.27 AC9.B
N$53
  Top 0.381: T53.3 235.59,45.72 236.22,45.09 236.22,41.27 AC10.B
N$54
  Bottom 0.381: T54.3 248.28,45.72 250.19,43.81 250.19,41.27 AC11.B
N$55
  Top 0.381: T55.3 92.71,25.4 93.34,24.77 93.34,20.32 MQ0.B
N$56
  Top 0.381: T56.3 106.68,24.77 107.31,24.13 107.31,20.32 MQ1.B
N$57
  Top 0.381: T57.3 121.28,25.4 121.92,24.77 121.92,20.32 MQ2.B
N$58
  Top 0.381: T58.3 135.25,24.77 135.89,24.13 135.89,20.32 MQ3.B
N$59
  Top 0.381: T59.3 149.86,25.4 150.5,24.77 150.5,20.32 MQ4.B
N$60
  Top 0.381: T60.3 163.83,24.77 164.47,24.13 164.47,20.32 MQ5.B
N$61
  Top 0.381: T61.3 178.44,25.4 179.07,24.77 179.07,20.32 MQ6.B
N$62
  Top 0.381: T62.3 192.41,24.77 193.04,24.13 193.04,20.32 MQ7.B
N$63
  Top 0.381: T63.3 207.01,25.4 207.65,24.77 207.65,20.32 MQ8.B
N$64
  Top 0.381: T64.3 220.98,24.77 221.62,24.13 221.62,20.32 MQ9.B
N$65
  Top 0.381: T65.3 235.59,25.4 236.22,24.77 236.22,20.32 MQ10.B
N$66
  Top 0.381: T66.3 249.56,24.77 250.19,24.13 250.19,20.32 MQ11.B
N$67
  Top 0.381: T67.3 5.08,24.77 5.71,24.13 5.71,20.32 SC0.B
N$68
  Top 0.381: T68.3 19.68,25.4 20.32,24.77 20.32,20.32 SC1.B
N$69
  Bottom 0.381: T69.3 33.66,24.77 34.29,24.13 34.29,20.32 SC2.B
N$70
  Bottom 0.381: T70.3 48.26,25.4 48.9,24.77 48.9,20.32 SC3.B
N$71
  Bottom 0.381: T71.3 62.23,24.77 62.87,24.13 62.87,20.32 SC4.B
N$72
  Bottom 0.381: T72.3 78.11,45.72 78.74,45.09 78.74,41.27 LINK.B
N$73
  Bottom 0.381: T73.3 357.5,105.41 363.22,105.41 364.49,106.68 ION.B
N$74
  Bottom 0.381: T74.3 357.5,93.98 363.22,93.98 363.22,94.61 364.49,95.89 PAUSE.B
N$75
  Top 0.381: T75.3 357.5,83.19 363.22,83.19 364.49,84.45 RUN.B
N$76
  Bottom 0.381: T76.3 344.17,107.31 337.19,107.31 FETCH.B
N$77
  Bottom 0.381: T77.3 344.17,96.52 337.19,96.52 EXECUTE.B
N$78
  Bottom 0.381: T78.3 344.17,85.09 337.19,85.09 DEFER.B
N$79
  Bottom 0.381: T79.3 344.17,74.3 337.19,74.3 WORDCOUNT.B
N$80
  Bottom 0.381: T80.3 344.17,62.87 337.19,62.87 CURRENTADDRESS.B
N$81
  Bottom 0.381: T81.3 344.17,52.07 337.19,52.07 BREAK.B
N$82
  Top 0.381: T82.3 315.6,107.31 308.61,107.31 AND.B
N$83
  Bottom 0.381: T83.3 315.6,96.52 308.61,96.52 TAD.B
N$84
  Bottom 0.381: T84.3 315.6,85.09 308.61,85.09 ISZ.B
N$85
  Bottom 0.381: T85.3 315.6,74.3 308.61,74.3 DCA.B
N$86
  Bottom 0.381: T86.3 315.6,62.87 308.61,62.87 JMS.B
N$87
  Bottom 0.381: T87.3 315.6,52.07 308.61,52.07 JMP.B
N$88
  Bottom 0.381: T88.3 315.6,40.64 308.61,40.64 IOT.B
N$89
  Bottom 0.381: T89.3 315.6,29.84 308.61,29.84 OPR.B
N$90
  Top 0.381: R1.2 7.62,101.6 7.62,104.14 DF0.A
N$91
  Top 0.381: R2.2 22.23,102.23 22.23,104.14 DF1.A
N$92
  Top 0.381: R3.2 36.2,101.6 36.2,104.14 DF2.A
N$93
  Top 0.381: R4.2 50.8,102.23 50.8,104.14 IF0.A
N$94
  Top 0.381: R5.2 64.77,101.6 64.77,104.14 IF1.A
N$95
  Top 0.762: R6.2 79.38,102.23 79.38,104.14 IF2.A
N$96
  Top 0.381: R7.2 93.34,101.6 93.34,104.14 PC0.A
N$97
  Top 0.381: R8.2 107.95,102.23 107.95,104.14 PC1.A
N$98
  Top 0.381: R9.2 121.92,101.6 121.92,104.14 PC2.A
N$99
  Top 0.381: R10.2 136.53,102.23 136.53,104.14 PC3.A
N$100
  Top 0.381: R11.2 150.5,101.6 150.5,104.14 PC4.A
N$101
  Top 0.381: R12.2 165.1,102.23 165.1,104.14 PC5.A
N$102
  Top 0.381: R13.2 179.07,101.6 179.07,104.14 PC6.A
N$103
  Top 0.381: R14.2 193.68,102.23 193.68,104.14 PC7.A
N$104
  Top 0.381: R15.2 207.65,101.6 207.65,104.14 PC8.A
N$105
  Top 0.381: R16.2 222.25,102.23 222.25,104.14 PC9.A
N$106
  Top 0.381: R17.2 236.22,101.6 236.22,104.14 PC10.A
N$107
  Top 0.381: R18.2 250.82,102.23 250.82,104.14 PC11.A
N$108
  Top 0.381: R73.2 364.49,101.6 364.49,104.14 ION.A
N$109
  Top 0.381: R74.2 365.12,90.81 365.12,93.34 PAUSE.A
N$110
  Top 0.381: R75.2 365.12,80.01 365.12,81.92 RUN.A
N$111
  Top 0.381: R19.2 93.34,79.38 93.34,81.92 MA0.A
N$112
  Top 0.381: R20.2 107.95,80.01 107.95,81.92 MA1.A
N$113
  Top 0.381: R21.2 121.92,79.38 121.92,81.92 MA2.A
N$114
  Top 0.381: R22.2 136.53,80.01 136.53,81.92 MA3.A
N$115
  Top 0.381: R23.2 150.5,79.38 150.5,81.92 MA4.A
N$116
  Top 0.381: R24.2 165.1,80.01 165.1,81.92 MA5.A
N$117
  Top 0.381: R25.2 179.07,79.38 179.07,81.92 MA6.A
N$118
  Top 0.381: R26.2 193.68,80.01 193.68,81.92 MA7.A
N$119
  Top 0.381: R27.2 207.65,79.38 207.65,81.92 MA8.A
N$120
  Top 0.381: R28.2 222.25,80.01 222.25,81.92 MA9.A
N$121
  Top 0.381: R29.2 236.22,79.38 236.22,81.92 MA10.A
N$122
  Top 0.381: R30.2 250.82,80.01 250.82,81.92 MA11.A
N$123
  Top 0.381: R76.2 336.55,102.23 336.55,104.14 FETCH.A
N$124
  Top 0.381: R77.2 336.55,90.81 336.55,93.34 EXECUTE.A
N$125
  Top 0.381: R78.2 336.55,80.01 336.55,81.92 DEFER.A
N$126
  Top 0.381: R79.2 336.55,68.58 336.55,71.12 WORDCOUNT.A
N$127
  Top 0.381: R80.2 336.55,57.78 336.55,59.69 CURRENTADDRESS.A
N$128
  Top 0.381: R81.2 336.55,46.35 336.55,48.9 BREAK.A
N$129
  Top 0.381: R72.2 79.38,35.56 79.38,37.47 LINK.A
N$130
  Top 0.381: R31.2 93.34,57.15 93.34,59.69 MB0.A
N$131
  Top 0.381: R32.2 107.95,57.78 107.95,59.69 MB1.A
N$132
  Top 0.381: R33.2 121.92,57.15 121.92,59.69 MB2.A
N$133
  Top 0.381: R34.2 136.53,57.78 136.53,59.69 MB3.A
N$134
  Top 0.381: R35.2 150.5,57.15 150.5,59.69 MB4.A
N$135
  Top 0.381: R36.2 165.1,57.78 165.1,59.69 MB5.A
N$136
  Top 0.381: R37.2 179.07,57.15 179.07,59.69 MB6.A
N$137
  Top 0.381: R38.2 193.68,57.78 193.68,59.69 MB7.A
N$138
  Top 0.381: R39.2 207.65,57.15 207.65,59.69 MB8.A
N$139
  Top 0.381: R40.2 222.25,57.78 222.25,59.69 MB9.A
N$140
  Top 0.381: R41.2 236.22,57.15 236.22,59.69 MB10.A
N$141
  Top 0.381: R42.2 250.82,57.78 250.82,59.69 MB11.A
N$142
  Top 0.381: R43.2 93.34,34.92 93.34,37.47 AC0.A
N$143
  Top 0.381: R44.2 107.95,35.56 107.95,37.47 AC1.A
N$144
  Top 0.381: R45.2 121.92,34.92 121.92,37.47 AC2.A
N$145
  Top 0.381: R46.2 136.53,35.56 136.53,37.47 AC3.A
N$146
  Top 0.381: R47.2 150.5,35.56 150.5,37.47 AC4.A
N$147
  Top 0.381: R48.2 165.1,35.56 165.1,37.47 AC5.A
N$148
  Top 0.381: R49.2 179.07,34.92 179.07,37.47 AC6.A
N$149
  Top 0.381: R50.2 193.68,35.56 193.68,37.47 AC7.A
N$150
  Top 0.381: R51.2 207.65,35.56 207.65,37.47 AC8.A
N$151
  Top 0.381: R52.2 222.25,35.56 222.25,37.47 AC9.A
N$152
  Top 0.381: R53.2 236.22,34.92 236.22,37.47 AC10.A
N$153
  Top 0.381: R54.2 250.82,35.56 250.82,37.47 AC11.A
N$154
  Top 0.381: R67.2 6.35,14.61 6.35,17.14 SC0.A
N$155
  Top 0.381: R68.2 20.32,14.61 20.32,17.14 SC1.A
N$156
  Top 0.381: R69.2 34.92,14.61 34.92,17.14 SC2.A
N$157
  Bottom 0.381: R70.2 48.9,14.61 48.9,17.14 SC3.A
N$158
  Top 0.381: R71.2 63.5,14.61 63.5,17.14 SC4.A
N$159
  Top 0.381: R66.2 250.82,14.61 250.82,17.14 MQ11.A
N$160
  Top 0.381: R65.2 236.22,14.61 236.22,17.14 MQ10.A
N$161
  Top 0.381: R64.2 222.25,14.61 222.25,17.14 MQ9.A
N$162
  Top 0.381: R63.2 207.65,14.61 207.65,17.14 MQ8.A
N$163
  Top 0.381: R62.2 193.68,14.61 193.68,17.14 MQ7.A
N$164
  Top 0.381: R61.2 179.07,14.61 179.07,17.14 MQ6.A
N$165
  Top 0.381: R60.2 165.1,14.61 165.1,17.14 MQ5.A
N$166
  Top 0.381: R59.2 150.5,14.61 150.5,17.14 MQ4.A
  Top 0.762: R59.2 150.5,14.61 | 150.5,17.14 MQ4.A
N$167
  Top 0.381: R58.2 136.53,14.61 136.53,17.14 MQ3.A
N$168
  Top 0.381: R57.2 121.92,14.61 121.92,17.14 MQ2.A
N$169
  Top 0.381: R56.2 107.95,14.61 107.95,17.14 MQ1.A
N$170
  Top 0.381: R55.2 93.34,14.61 93.34,17.14 MQ0.A
  Top 0.762: R55.2 93.34,14.61 | 93.34,17.14 MQ0.A
N$171
  Top 0.381: R82.2 307.98,102.23 307.98,104.14 AND.A
N$172
  Top 0.381: R83.2 307.98,90.81 307.98,93.34 TAD.A
N$173
  Top 0.381: R84.2 307.98,80.01 307.98,81.92 ISZ.A
N$174
  Top 0.381: R85.2 307.98,68.58 307.98,71.12 DCA.A
N$175
  Top 0.381: R86.2 307.98,57.78 307.98,59.69 JMS.A
N$176
  Top 0.381: R87.2 307.98,46.35 307.98,48.9 JMP.A
N$177
  Top 0.381: R88.2 307.98,35.56 307.98,37.47 IOT.A
N$178
  Top 0.381: R89.2 307.98,24.13 307.98,26.67 OPR.A
OPR
  Top 0.381: T89.2 318.13,28.57 327.66,38.1 327.66,120.65 D40.16 328.3,121.28 328.93,121.92 328.93,124.46 329.56,125.09 329.56,128.27 330.2,128.91 F40BOT.11
PAUSE
  Bottom 0.381: 344.81,125.09 344.17,124.46 344.17,120.02 349.25,114.94 349.25,100.97 354.96,95.25 T74.2 | 344.81,125.09 347.35,125.09 347.35,123.83 D40.31 | 344.81,125.09 344.81,132.72 340.36,132.72 340.36,132.08 339.73,131.44 F40TOP.17
PC0
  Top 0.381: T7.2 93.98,114.94 103.5,124.46 106.05,124.46 106.05,123.83 E40.1
  Bottom 0.381: D40TOP.1 114.3,128.91 106.68,128.91 106.68,127.64 93.98,114.94 T7.2
PC1
  Top 0.381: 115.57,114.94 116.2,114.94 116.2,120.65 E40.10 | 115.57,114.94 107.95,114.94 T8.2 | 115.57,114.94 115.57,125.09 117.47,125.09 120.02,127.64 120.02,128.27 120.65,128.91 D40BOT.5
PC2
  Top 0.381: T9.2 121.92,114.94 120.65,116.2 120.65,122.56 120.02,123.19 E40.11
  Bottom 0.381: D40TOP.6 121.92,128.91 121.92,125.73 120.02,123.83 E40.11
PC3
  Top 0.381: T10.2 136.53,114.94 135.25,116.2 135.25,120.65 E40.24 133.99,121.28 133.35,121.92 133.35,124.46 134.62,125.73 134.62,128.91 D40BOT.14
PC4
  Top 0.381: T11.2 150.5,114.94 138.43,114.94 138.43,122.56 137.79,123.19 E40.25
  Bottom 0.381: D40TOP.14 135.25,128.91 135.25,125.09 136.53,123.83 E40.25
PC5
  Top 0.381: D40BOT.19 142.88,128.91 146.05,125.73 146.05,121.92 146.69,121.28 E40.34
  Bottom 0.381: T12.2 165.1,114.94 152.4,114.94 152.4,116.2 147.96,120.65 E40.34
PC6
  Bottom 0.381: E40TOP.1 200.03,128.91 193.68,128.91 179.71,114.94 T13.2 179.07,114.3 177.16,114.3 176.53,113.67 176.53,88.9 181.61,88.9 182.88,90.17 182.88,111.12 194.94,123.19 F40.1
PC7
  Top 0.381: 204.47,114.94 205.1,114.94 205.1,120.65 F40.10 | 204.47,114.94 193.68,114.94 T14.2 | 204.47,114.94 204.47,124.46 205.74,125.73 205.74,128.27 206.38,128.91 E40BOT.5
PC8
  Top 0.381: T15.2 207.65,114.94 207.01,115.57 207.01,122.56 207.65,123.19 F40.11
  Bottom 0.381: E40TOP.6 207.65,128.91 207.65,123.83 F40.11
PC9
  Top 0.381: 222.25,114.94 222.88,115.57 222.88,120.65 F40.24 | 222.25,114.94 T16.2 222.25,114.94 | 222.25,114.94 222.25,124.46 220.98,125.73 220.98,128.91 E40BOT.14
PC10
  Top 0.381: T17.2 236.22,114.94 227.33,114.94 227.33,122.56 226.69,123.19 F40.25
  Bottom 0.381: E40TOP.14 220.98,128.91 220.98,128.27 225.43,123.83 F40.25
PC11
  Top 0.381: E40BOT.19 228.6,128.91 250.82,128.91 250.82,114.94 T18.2
  Bottom 0.381: T18.2 250.82,114.94 240.66,114.94 240.66,116.84 236.85,120.65 F40.34
RUN
  Top 0.381: T75.2 354.96,84.45 351.79,87.63 351.79,122.56 351.15,123.19 D40.33
  Bottom 0.381: F40TOP.18 341,128.91 341,126.36 339.09,124.46 339.09,112.39 334.64,107.95 334.64,92.71 335.28,92.08 367.03,92.08 367.03,107.95 351.15,123.83 D40.33
SC0
  Bottom 0.381: T67.2 6.35,27.94 33.66,55.24 33.66,119.38 33.02,120.02 33.02,122.56 33.66,123.19 C40.9 34.92,123.83 34.92,128.91 C40TOP.5
SC1
  Top 0.381: 25.4,128.91 28.57,128.91 C40BOT.1 | 25.4,128.91 12.7,128.91 5.08,121.28 5.08,42.55 20.32,27.3 T68.2 | 25.4,128.91 25.4,121.92 24.77,121.28 C40.2
SC2
  Bottom 0.381: T69.2 34.92,27.94 53.98,46.99 53.98,119.38 53.34,120.02 53.34,122.56 52.7,123.19 C40.23 51.44,123.83 48.26,127 48.26,128.27 47.62,128.91 C40TOP.13
SC3
  Top 0.381: 38.1,120.02 37.47,120.65 C40.12 | 38.1,120.02 39.37,118.75 39.37,109.86 36.2,109.86 31.11,104.78 31.11,45.09 48.9,27.3 T70.2 | 38.1,120.02 38.1,124.46 36.83,125.73 36.83,128.91 C40BOT.6
SC4
  Bottom 0.381: 55.88,125.09 55.88,128.91 C40TOP.18 | 55.88,125.09 55.88,35.56 63.5,27.94 T71.2 | 55.88,125.09 62.87,125.09 64.14,123.83 C40.33
TAD
  Top 0.381: T83.2 318.13,95.25 319.4,96.52 319.4,114.3 313.06,120.65 D40.4 311.79,121.28 311.15,121.92 311.15,125.09 312.42,125.09 315.6,128.27 315.6,128.91 F40BOT.2
WC
  Top 0.381: F40BOT.17 339.73,128.91 340.36,128.27 340.36,127.64 342.9,125.09 343.54,125.09 344.17,124.46 344.17,121.92 344.81,121.28 D40.30
  Bottom 0.381: T79.2 346.71,73.03 349.25,70.48 349.25,50.16 332.74,33.66 292.74,33.66 292.74,111.76 314.96,133.99 349.25,133.99 349.25,120.02 348.62,119.38 346.07,119.38 346.07,120.65 D40.30

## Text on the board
Bottom: PDP-8/I Light Board 50045108 | 5404519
